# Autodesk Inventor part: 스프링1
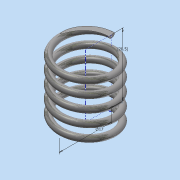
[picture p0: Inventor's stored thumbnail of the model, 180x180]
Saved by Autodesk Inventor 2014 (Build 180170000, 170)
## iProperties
Created: 2016-03
Part Number: 스프링1
Material: 스테인레스 스틸
Document SubType Name: Modeling
Designer: SCD-A13
Density: 8.08 g/cm^3
Appearance: 반연마
Mass: 6.63802 g
Surface Area: 16.7216 cm^2
Volume: 0.821537 cm^3
Author: SCD-A13
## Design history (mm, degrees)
sketch "스케치1"
  geometry: L1 (0, 20.5)-(8.5, 20.5); L2 (8.5, 20.5)-(8.5, 0); L3 (8.5, 0)-(0, 0); L4 (0, 0)-(0, 20.5); C1 r 1 at (8.5, 0); 1 further point
  constraints: 8 end point, 2 coincident, 2 parallel, 1 centre point, 1 horizontal, 1 perpendicular
  dimensions: "d0" = 2 diameter of C1; "d1" = 17 diameter of L2 L4; "d2" = 20.5 distance between parallel lines of L1 L3 (derived)
feature "코일1" pitch "d3" = 10; turns "d5" = 5; dims "d4" = 20.5 (= d2), "d6" = 0, angle "d7" = 90 deg, angle "d8" = 90 deg, "d9" = 0, "d10" = 0
node "작업 평면1"
sketch "스케치2"
  geometry: L1 (1, 0)-(-1, 0) reference; 1 further point
  constraints: 1 horizontal alignment
extrude "돌출1" cut sketch "스케치2" stored distance "d12" = 10; taper "d13" = 0 deg
node "작업 평면2"
sketch "스케치3"
  geometry: L1 (9.5, 0)-(7.5, 0) reference; 1 further point
  constraints: 1 horizontal alignment
extrude "돌출2" cut sketch "스케치3" stored distance "d15" = 10; taper "d16" = 0 deg
node "솔리드1"
node "절단 모서리 투영1"
node "절단 모서리 투영2"
other parameters: "d11" = 0, "d14" = 0
